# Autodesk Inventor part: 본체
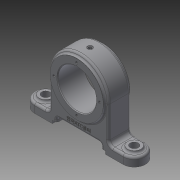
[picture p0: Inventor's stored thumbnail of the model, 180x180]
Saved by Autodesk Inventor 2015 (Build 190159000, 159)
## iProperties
Created: 2019-05
Part Number: 본체
Material: 알루미늄 6061
Document SubType Name: Modeling
Designer: CAD02
Density: 2.7 g/cm^3
Appearance: 기본값
Mass: 454.985 g
Surface Area: 318.799 cm^2
Volume: 168.513 cm^3
Author: CAD02
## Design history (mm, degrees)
sketch "스케치1"
  geometry: L1 (75, 15)-(-75, 15); L2 (-75, 15)-(-75, -15); L3 (-75, -15)-(75, -15); L4 (75, -15)-(75, 15); L5 (75, 15)-(-75, -15); L6 (-75, 15)-(75, -15); 1 further point
  constraints: 12 end point, 2 midpoint, 2 parallel, 1 horizontal, 1 perpendicular
  dimensions: "d0" = 30 distance of L1.end L2.end; "d1" = 150 distance of L1.start L1.end
extrude "돌출1" new body sketch "스케치1" distance "d2" = 12; taper "d3" = 0 deg
fillet "모깎기1" dims "d4" = 15
sketch "스케치2"
  geometry: C1 r 9 at (-60, 0); A1 r 15 centre (-60, 0) between (-60, 15) and (-60, -15) reference; 1 further point
  constraints: 1 centre point, 1 coincident
  dimensions: "d5" = 18 diameter of C1
extrude "돌출2" join sketch "스케치2" distance "d6" = 3; taper "d7" = 0 deg
sketch "스케치3"
  geometry: C1 r 9 at (0, 0) reference; 1 further point
hole "구멍1" sketch "스케치3" at (0, 0) diameter "d8" = 11; stored, may be unused: countersink angle "d12" = 90 deg, drill point angle "d14" = 0 deg; dims "d9" = 6, "d10" = 4, "d11" = 2, "d13" = 8
sketch "스케치4"
  geometry: L1 (0, 0)-(120, 0) reference; L2 (30, 0)-(90, 0); L3 (90, 0)-(90, 10); L4 (90, 10)-(30, 10); L5 (30, 10)-(30, 0); 3 further points
  constraints: 8 end point, 2 midpoint, 2 parallel, 1 coincident, 1 horizontal, 1 perpendicular, 1 point on line
  dimensions: "d15" = 10 distance of L2.end L3.end; "d16" = 60 distance between parallel lines of L3 L5
extrude "돌출3" cut sketch "스케치4" stored distance "d18" = 3; taper "d19" = 0 deg
sketch "스케치5"
  geometry: L1 (0, -12)-(30, -12) reference; L2 (24, -12)-(96, -12); L3 (96, -12)-(96, -8); L4 (96, -8)-(24, -8); L5 (24, -8)-(24, -12); 2 further points
  constraints: 8 end point, 2 parallel, 1 coincident, 1 horizontal, 1 midpoint, 1 perpendicular, 1 point on line
  dimensions: "d20" = 4 distance of L4.end L2.start; "d21" = 72 distance of L3.end L4.end
extrude "돌출4" cut sketch "스케치5" stored distance "d22" = 3; taper "d23" = 0 deg
sketch "스케치6"
  geometry: L1 (-60, -15)-(60, -15) reference; L2 (40, 15)-(-40, 15); L3 (-40, 15)-(-40, -15); L4 (-40, -15)-(40, -15); L5 (40, -15)-(40, 15); L6 (40, 15)-(-40, -15); L7 (-40, 15)-(40, -15); 1 further point
  constraints: 12 end point, 2 midpoint, 2 parallel, 1 horizontal, 1 perpendicular, 1 point on line
  dimensions: "d24" = 80 distance between parallel lines of L3 L5
extrude "돌출5" join sketch "스케치6" distance "d25" = 48; taper "d26" = 0 deg
sketch "스케치7"
  geometry: L1 (-20, 60)-(-100, 60) reference; 2 further points
  constraints: 1 horizontal alignment, 1 midpoint, 2 other
extrude "돌출6" join sketch "스케치7" distance "d27" = 30; taper "d28" = 0 deg
sketch "스케치8"
  geometry: L1 (75, 0)-(65.5, 0) reference; L2 (65.5, 0)-(65.5, 15) reference; L3 (65.5, 15)-(69, 15) reference; L4 (69, 15)-(69, 12) reference; L5 (69, 12)-(75, 12) reference; L6 (75, 12)-(75, 0) reference; L7 (-54.5, 0)-(-54.5, 15) reference; L8 (-54.5, 15)-(-51, 15) reference; L9 (-51, 15)-(-51, 12) reference; L10 (-51, 12)-(-40, 12) reference; L11 (-40, 12)-(-40, 60) reference; L12 (40, 60)-(40, 12) reference; L13 (40, 12)-(51, 12) reference; L14 (51, 12)-(51, 15) reference; L15 (51, 15)-(54.5, 15) reference; L16 (54.5, 15)-(54.5, 0) reference; L17 (54.5, 0)-(36, 0) reference; L18 (36, 0)-(36, 4) reference; L19 (36, 4)-(30, 4) reference; L20 (30, 4)-(30, 10) reference; L21 (30, 10)-(-30, 10) reference; L22 (-30, 10)-(-30, 4) reference; L23 (-30, 4)-(-36, 4) reference; L24 (-36, 4)-(-36, 0) reference; L25 (-36, 0)-(-54.5, 0) reference; L26 (-65.5, 15)-(-65.5, 0) reference; L27 (-65.5, 0)-(-75, 0) reference; L28 (-75, 0)-(-75, 12) reference; L29 (-75, 12)-(-69, 12) reference; L30 (-69, 12)-(-69, 15) reference; L31 (-69, 15)-(-65.5, 15) reference; C1 r 36 at (0, 60); A1 r 40 centre (0, 60) between (40, 60) and (-40, 60) reference; 1 further point
  constraints: 1 centre point, 1 coincident
  dimensions: "d29" = 72 diameter of C1
extrude "돌출7" join sketch "스케치8" stored distance "d30" = 36; taper "d31" = 0 deg
sketch "스케치9"
  geometry: C1 r 36 at (0, 0) reference; 1 further point
hole "구멍2" sketch "스케치9" at (0, 0) diameter "d32" = 52; stored, may be unused: countersink angle "d36" = 90 deg, drill point angle "d38" = 0 deg; dims "d33" = 6, "d34" = 4, "d35" = 2, "d37" = 8
sketch "스케치10"
  geometry: C1 r 26 at (0, 0) reference; 2 further points
  constraints: 1 vertical alignment
  dimensions: "d82" = 31 distance of C1.centre point (0, 31)
hole "구멍3" sketch "스케치10" at (0, 31) diameter "d39" = 3.242; stored, may be unused: countersink angle "d43" = 90 deg, drill point angle "d45" = 118 deg; dims "d40" = 6, "d41" = 4, "d42" = 2, "d44" = 8
node "작업 평면1"
sketch "스케치11"
  geometry: C1 r 3.5 at (0, 0); 1 further point
  constraints: 1 centre point, 1 coincident
  dimensions: "d50" = 7 diameter of C1
extrude "돌출8" cut sketch "스케치11" distance "d51" = 1; taper "d52" = 0 deg
sketch "스케치12"
  geometry: C1 r 3.5 at (0, 0) reference
hole "구멍4" sketch "스케치12" at (0, 0) diameter "d53" = 4.917; stored, may be unused: countersink angle "d57" = 90 deg, drill point angle "d59" = 118 deg; dims "d54" = 7, "d55" = 4, "d56" = 2, "d58" = 9
sketch "스케치13"
  geometry: C1 r 2.458 at (0, 0) reference
hole "구멍5" sketch "스케치13" at (0, 0) diameter "d60" = 2; stored, may be unused: countersink angle "d64" = 90 deg, drill point angle "d66" = 0 deg; dims "d61" = 8, "d62" = 4, "d63" = 2, "d65" = 36
sketch "스케치14"
  geometry: 3 further points
  constraints: 2 vertical alignment, 1 other
hole "구멍6" sketch "스케치14" at (0, 26) diameter "d67" = 3; stored, may be unused: countersink angle "d71" = 90 deg, drill point angle "d73" = 0 deg; dims "d68" = 8, "d69" = 4, "d70" = 2, "d72" = 36
fillet "모깎기2" dims "d74" = 6
fillet "모깎기3" dims "d75" = 3
fillet "모깎기4" dims "d76" = 3
fillet "모깎기5" dims "d77" = 3
fillet "모깎기6" dims "d78" = 3
chamfer "모따기1" distance "d79" = 1; stored, may be unused: second distance "d80" = 2, angle "d81" = 45 deg
sketch "스케치15"
  geometry: L1 (-63, 10)-(-9, 10) reference; 2 further points
  constraints: 1 vertical alignment, 1 other
  dimensions: "d83" = 7 distance from line of L1 point (-36, 17)
feature "엠보싱1" sketch "스케치15" dims "d0" = 30, "d1" = 150, "d84" = 0.5, "d85" = 0
node "솔리드1"
mirror "대칭1"
pattern_circular "원형 패턴1" dims angle "d47" = 360 deg
mirror "대칭2"
node "절단 모서리 투영1"
